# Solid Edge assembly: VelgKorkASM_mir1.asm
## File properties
Author: KULL
Template: Iso Metric Assembly.asm
Last saved by: KULL
Revision: 2
Application: Solid Edge
Username: KULL
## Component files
Velg2_mir1.par
VeljekorkASM_mir1.asm
Rehv1_mir1.par
VelgKorkASM.asm
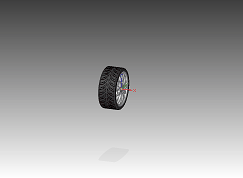
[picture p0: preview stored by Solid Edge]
